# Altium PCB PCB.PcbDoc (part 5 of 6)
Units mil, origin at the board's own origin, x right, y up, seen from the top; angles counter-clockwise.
Board outline 7100 x 7000 mil, 4 copper layers (Top Layer, GND, VCC, Bottom Layer), stack 61.2 mil thick; 759 components, 507 nets, 2200 pads, 452 vias.
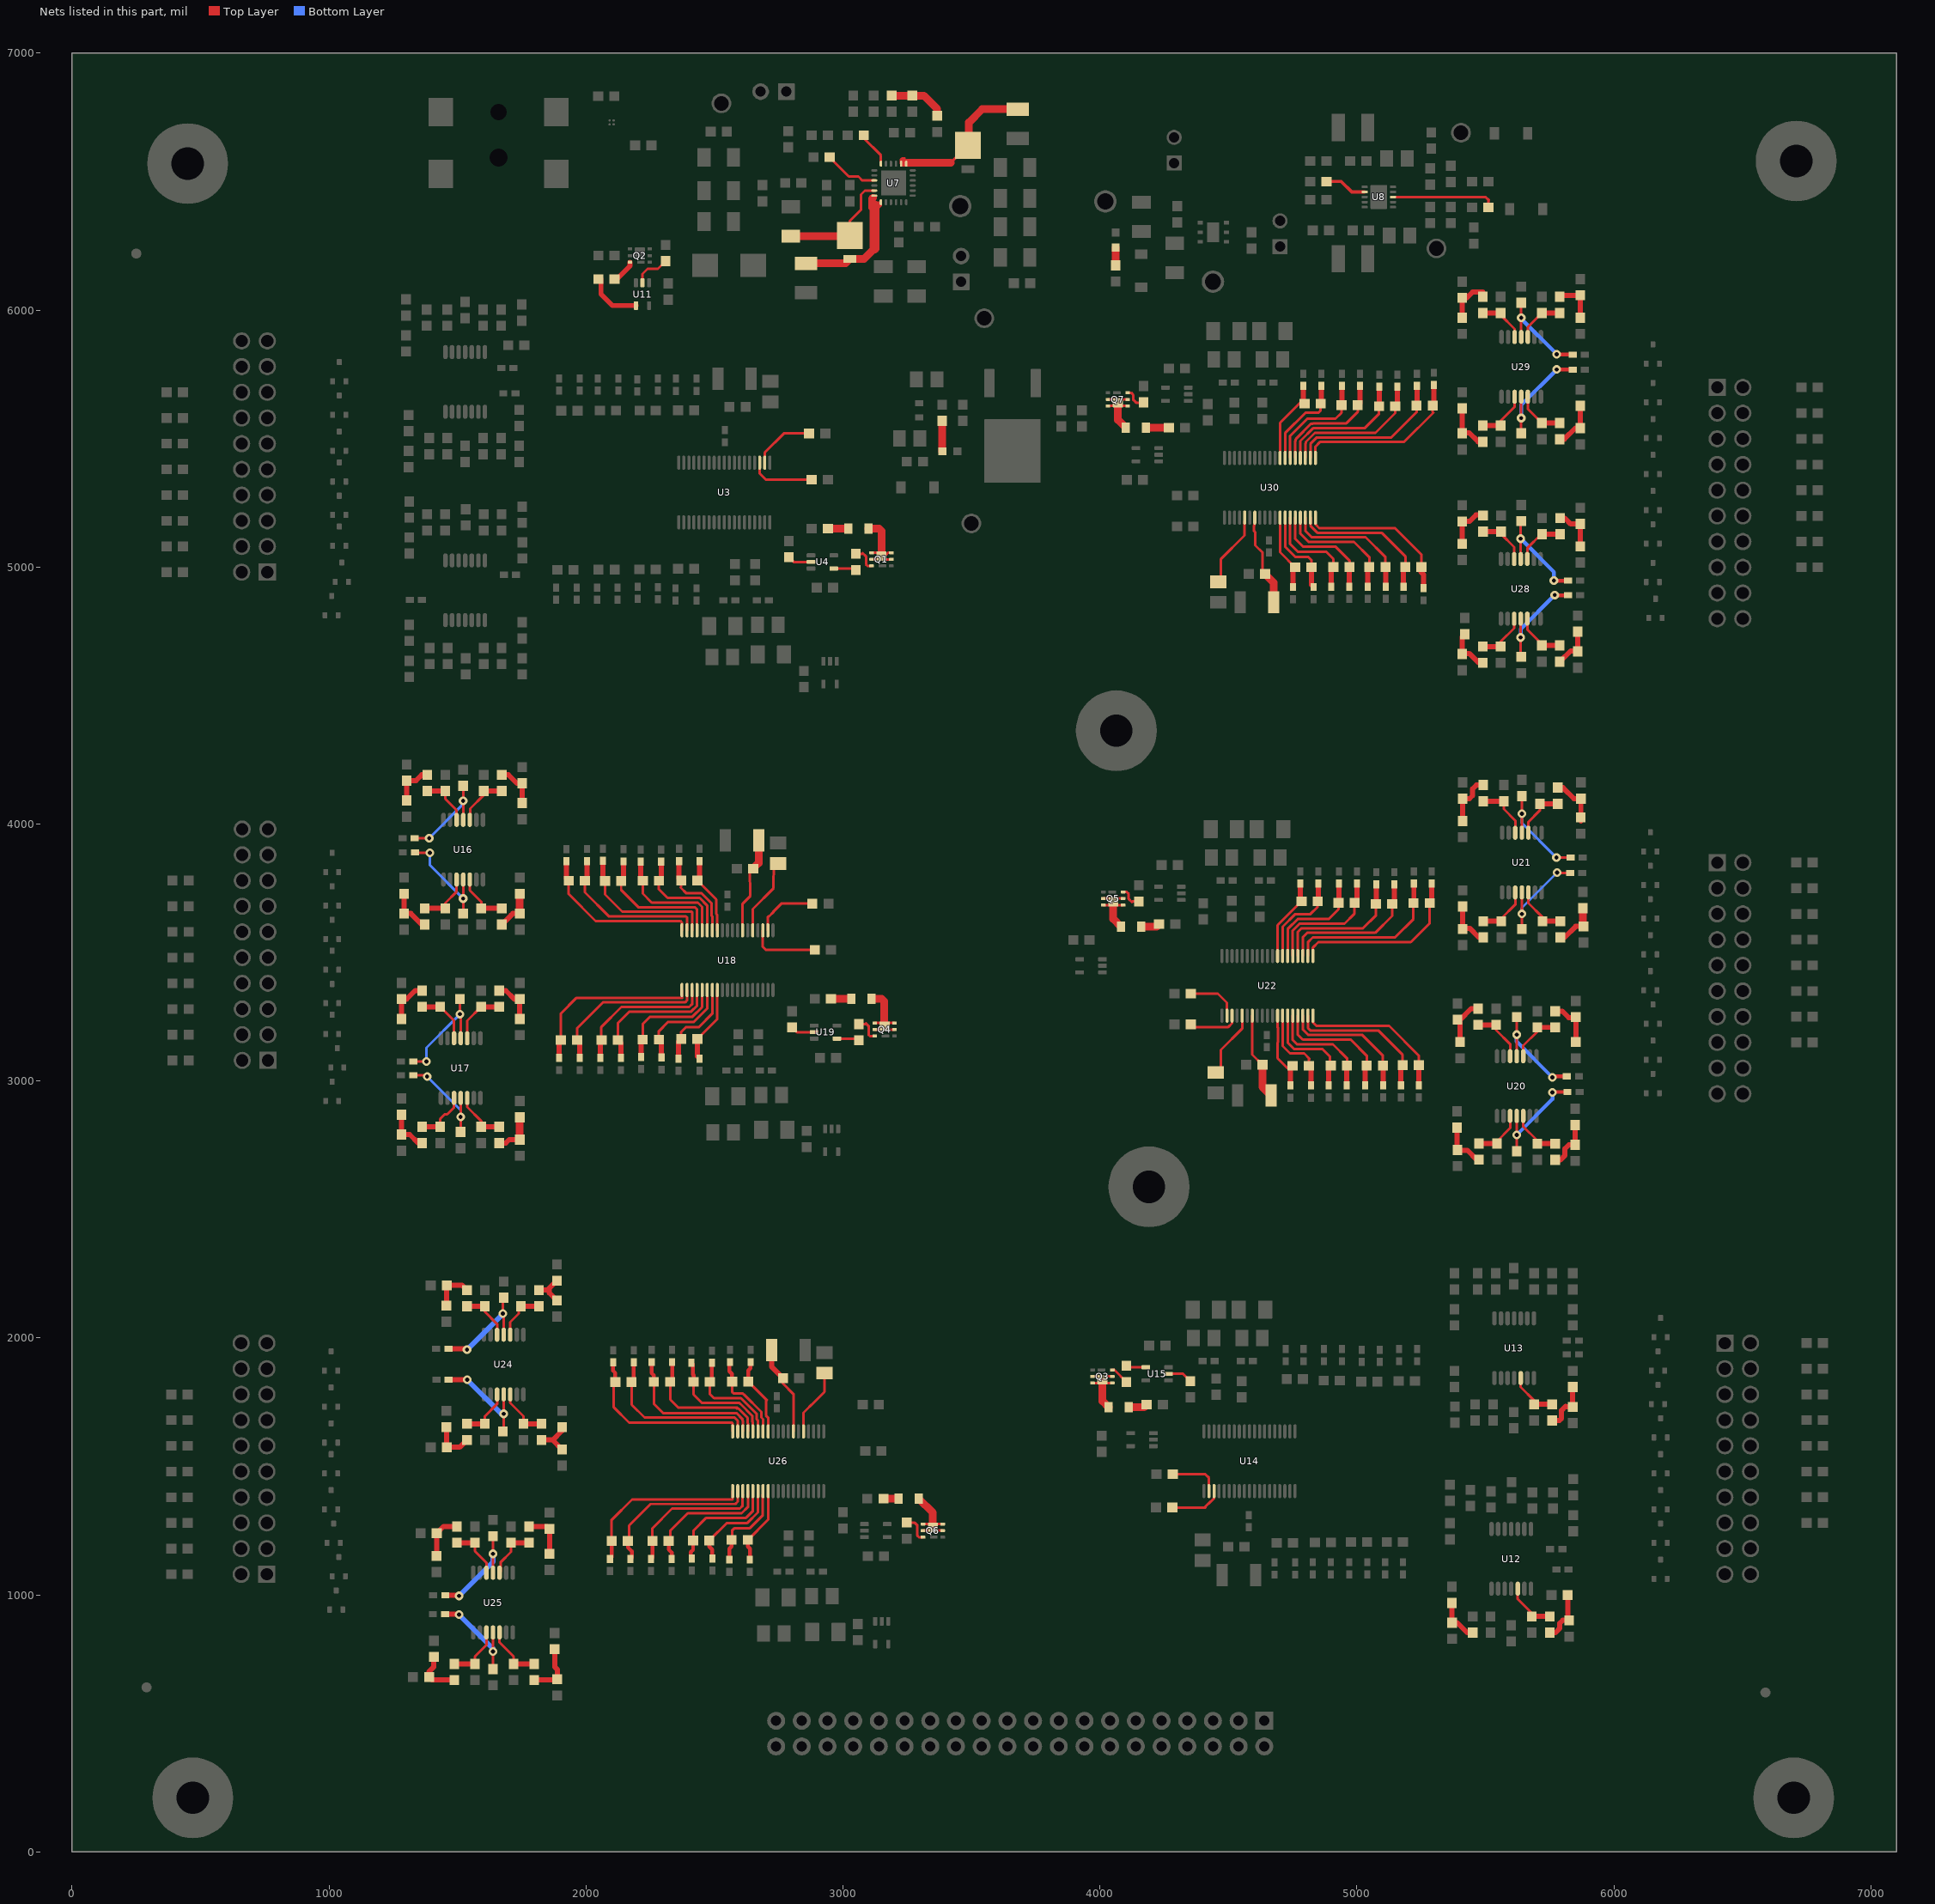
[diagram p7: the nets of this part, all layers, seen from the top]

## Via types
v1: diameter 34, hole 16, Top Layer to Bottom Layer, 440 vias
v2: diameter 19.68, hole 7.87, Top Layer to Bottom Layer, 11 vias
v3: diameter 30, hole 14, Top Layer to Bottom Layer, 1 vias

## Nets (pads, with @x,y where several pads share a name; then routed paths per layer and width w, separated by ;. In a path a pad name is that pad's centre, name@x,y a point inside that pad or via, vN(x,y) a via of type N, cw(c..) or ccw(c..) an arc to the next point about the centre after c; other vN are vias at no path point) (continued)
NetC108_2: C108.2 R109.2 R110.1 | length 173.3
  Top Layer w20: C108.2@5370,968.5 5370,892.22 R109.2@5370.73,891.5 5390.69,891.5 5429.23,852.95 R110.1@5450.73,852.95
NetC110_2: C110.2 R113.2 U12.5 | length 200.5
  Top Layer w10: U12.5@5626.32,1023.86 5626.32,983.68 5680.73,929.27 C110.2@5680.73,915.94
  Top Layer w20: C110.2@5680.73,915.94 R113.2@5750.73,915.94
NetC111_2: C111.2 R117.2 U13.5 | length 194.1
  Top Layer w10: U13.5@5637.64,1843.86 5637.64,1808.82 5690,1756.46 C111.2@5690,1741.5
  Top Layer w20: C111.2@5690,1741.5 R117.2@5760,1741.5
NetC112_2: C112.2 R112.2 R113.1 | length 203
  Top Layer w20: R113.1@5750.73,852.95 5772.95,852.95 5790,870 5790,890 5801.5,901.5 5830.73,901.5 5820.73,911.5 C112.2@5820.73,988.5
NetC113_2: C113.2 R116.2 R117.1 | length 199.3
  Top Layer w20: R117.1@5760,1678.5 5788.5,1678.5 5796.57,1686.57 5796.57,1717.84 5812.73,1734 5815.24,1731.5 R116.2@5840,1731.5 C113.2@5840,1808.5
NetC114_2: C114.2 R319.2 U16.4 | length 388.6
  Top Layer w10: R319.2@1333.62,3945 v1(1390,3945) ; U16.4@1522.36,4016.14 v1(1522.36,4090) C114.2@1522.36,4148.5
  Bottom Layer w10: v1(1390,3945) 1522.36,4077.36 v1(1522.36,4090)
NetC115_2: C115.2 R320.2 U17.4 | length 443.4
  Top Layer w10: R320.2@1327.62,3075 1378,3075 v1(1379,3076) ; C115.2@1510,3318.5 v1(1510,3260) 1512.36,3257.64 U17.4@1512.36,3166.14
  Bottom Layer w10: v1(1379,3076) 1379,3129 v1(1510,3260)
NetC116_2: C116.2 R119.2 U16.10 | length 210.8
  Top Layer w10: C116.2@1452.36,3671.5 1452.36,3692.36 1496.77,3736.77 U16.10@1496.77,3783.86
  Top Layer w20: R119.2@1372.36,3671.5 C116.2@1452.36,3671.5
NetC117_2: C117.2 R121.2 U17.10 | length 210.8
  Top Layer w10: C117.2@1432.36,2821.5 1432.36,2852.36 1450,2870 1460,2870 1486.77,2896.77 U17.10@1486.77,2933.86
  Top Layer w20: R121.2@1362.36,2821.5 C117.2@1432.36,2821.5
NetC124_2: C124.2 R321.2 U16.11 | length 422.7
  Top Layer w10: R321.2@1334.62,3889 1335.62,3888 v1(1393,3888) ; C124.2@1522.36,3651.5 v1(1522.36,3710) U16.11@1522.36,3783.86
  Bottom Layer w10: v1(1393,3888) 1393,3839.36 v1(1522.36,3710)
NetC125_2: C125.2 R322.2 U17.11 | length 399.8
  Top Layer w10: R322.2@1327.62,3022 1377,3022 v1(1382,3017) ; C125.2@1512.36,2801.5 v1(1512.36,2860) U17.11@1512.36,2933.86
  Bottom Layer w10: v1(1382,3017) 1512.36,2886.64 v1(1512.36,2860)
NetC126_2: C126.2 R118.2 R119.1 | length 174.8
  Top Layer w20: C126.2@1292.36,3728.5 R118.2@1292.36,3651.5 1318.5,3651.5 1361.5,3608.5 R119.1@1372.36,3608.5
NetC127_2: C127.2 R120.2 R121.1 | length 170.7
  Top Layer w20: C127.2@1282.36,2868.5 R120.2@1282.36,2791.5 1314.13,2791.5 1347.13,2758.5 R121.1@1362.36,2758.5
NetC128_1: C128.1 R130.2 U18.16 | length 523.2
  Top Layer w10: C128.1@2137.05,3778.12 2137.05,3742.95 2203.62,3676.38 2423.62,3676.38 2432.51,3667.49 U18.16@2432.51,3586.09
  Top Layer w20: C128.1@2137.05,3778.12 2145.55,3786.62 R130.2@2145.55,3854.5
NetC128_2: C128.2 R131.2 U18.17 | length 572.3
  Top Layer w10: C128.2@2074.06,3778.12 2074.06,3725.94 2141.5,3658.5 2411.5,3658.5 2412.82,3657.18 U18.17@2412.82,3586.09
  Top Layer w20: R131.2@2065.55,3856.38 2065.55,3786.62 C128.2@2074.06,3778.12
NetC129_1: C129.1 R132.2 U18.18 | length 613.9
  Top Layer w10: C129.1@1995.94,3778.7 1995.94,3734.06 2090,3640 2090.63,3640.63 2389.37,3640.63 2393.14,3636.86 U18.18@2393.14,3586.09
  Top Layer w20: C129.1@1995.94,3778.7 2004.45,3787.2 R132.2@2004.45,3855.64
NetC129_2: C129.2 R134.2 U18.19 | length 648.8
  Top Layer w10: C129.2@1932.95,3778.7 1932.95,3727.05 2037.64,3622.36 2082.36,3622.36 2082.6,3622.13 2097.4,3622.13 2098.03,3622.76 2367.24,3622.76 2373.45,3616.55 U18.19@2373.45,3586.09
  Top Layer w20: R134.2@1924.45,3855.08 1924.45,3787.2 C129.2@1932.95,3778.7
NetC130_2: C130.2 R136.2 U16.12 | length 210.8
  Top Layer w10: U16.12@1547.95,3783.86 1547.95,3742.05 1592.36,3697.64 C130.2@1592.36,3671.5
  Top Layer w20: C130.2@1592.36,3671.5 R136.2@1672.36,3671.5
NetC131_2: C131.2 R138.2 U17.12 | length 204.9
  Top Layer w10: U17.12@1537.95,2933.86 1537.95,2898.5 1592.36,2844.09 C131.2@1592.36,2821.5
  Top Layer w20: C131.2@1592.36,2821.5 R138.2@1662.36,2821.5
NetC132_1: C132.1 R139.2 U18.21 | length 633.2
  Top Layer w10: C132.1@1965.41,3159.59 1965.41,3205.41 2065.75,3305.75 2385.75,3305.75 2393.14,3313.14 U18.21@2393.14,3353.8
  Top Layer w20: C132.1@1965.41,3159.59 1975.86,3149.13 R139.2@1975.86,3089.59
NetC132_2: C132.2 R141.2 U18.20 | length 704.5
  Top Layer w10: C132.2@1902.42,3159.59 1902.42,3262.42 1963.62,3323.62 2375.11,3323.62 2373.45,3325.28 U18.20@2373.45,3353.8
  Top Layer w20: R141.2@1895.86,3089.59 1895.86,3153.03 C132.2@1902.42,3159.59
NetC133_1: C133.1 R142.2 U18.23 | length 537.1
  Top Layer w10: C133.1@2124.11,3159.59 2124.11,3224.11 2170,3270 2409.44,3270 2432.51,3293.06 U18.23@2432.51,3353.8
  Top Layer w20: C133.1@2124.11,3159.59 2135.88,3147.81 R142.2@2135.88,3089.59
NetC133_2: C133.2 R143.2 U18.22 | length 567.7
  Top Layer w10: C133.2@2061.12,3159.59 2060,3160.71 2060,3210 2137.87,3287.87 2402.04,3287.87 2412.82,3298.66 U18.22@2412.82,3353.8
  Top Layer w20: R143.2@2055.88,3089.59 2055.88,3154.35 C133.2@2061.12,3159.59
NetC134_1: C134.1 R144.2 U18.25 | length 403.3
  Top Layer w10: C134.1@2283.86,3161.22 2283.86,3193.86 2320,3230 2420,3230 2471.88,3281.88 U18.25@2471.88,3353.8
  Top Layer w20: C134.1@2283.86,3161.22 2294.09,3150.99 R144.2@2294.09,3091.22
NetC134_2: C134.2 R145.2 U18.24 | length 455.3
  Top Layer w10: C134.2@2220.87,3161.22 2220.87,3220.87 2250,3250 2414.72,3250 2452.19,3287.47 U18.24@2452.19,3353.8
  Top Layer w20: R145.2@2214.09,3093.62 2214.09,3154.45 C134.2@2220.87,3161.22
NetC135_2: C135.2 R135.2 R136.1 | length 165.2
  Top Layer w20: R136.1@1672.36,3608.5 1673.03,3608.5 1708.94,3644.41 1708.94,3645.08 1715.35,3651.5 R135.2@1742.36,3651.5
  Top Layer w30: R135.2@1742.36,3651.5 C135.2@1742.36,3728.5
NetC136_2: C136.2 R137.2 R138.1 | length 172.4
  Top Layer w20: R138.1@1662.36,2758.5 1688.5,2758.5 1701.5,2771.5 R137.2@1742.36,2771.5
  Top Layer w30: R137.2@1742.36,2771.5 C136.2@1742.36,2858.5
NetC137_1: C137.1 U18.5 | length 322.4
  Top Layer w10: U18.5@2649.04,3586.09 2649.04,3669.04 2730,3750 C137.1@2731,3850 ; C137.1@2730,3828.64 C137.1@2747.62,3846.26
NetC138_1: C138.1 C139.1 U18.7 | length 387.1
  Top Layer w10: U18.7@2609.67,3586.09 2609.67,3689.67 2640,3720 C139.1@2638.06,3826.26 ; C139.1@2640,3815.4 C139.1@2650.86,3826.26
  Top Layer w30: C139.1@2650.86,3826.26 2672.58,3847.98 C138.1@2672.58,3936.26
NetC140_1: C140.1 R146.2 U18.27 | length 302.2
  Top Layer w10: C140.1@2433.86,3163.57 2511.25,3240.96 U18.27@2511.25,3353.8
  Top Layer w20: C140.1@2433.86,3163.57 2433.86,3095.7 R146.2@2442.36,3087.19
NetC140_2: C140.2 R147.2 U18.26 | length 350.1
  Top Layer w10: C140.2@2370.87,3163.57 2370.87,3190.87 2390,3210 2440,3210 2491.56,3261.56 U18.26@2491.56,3353.8
  Top Layer w20: R147.2@2360.62,3087.19 2360.62,3153.32 C140.2@2370.87,3163.57
NetC141_1: C141.1 R148.2 U18.12 | length 305.3
  Top Layer w10: C141.1@2433.86,3779.95 2507.44,3706.37 2507.44,3649.89 2511.25,3646.09 U18.12@2511.25,3586.09
  Top Layer w20: C141.1@2433.86,3779.95 2442.36,3788.45 R148.2@2442.36,3855.82
NetC141_2: C141.2 R149.2 U18.13 | length 359.8
  Top Layer w10: C141.2@2370.87,3779.95 2370.87,3755.19 2368.36,3752.68 2391.05,3730 2450,3730 2489.57,3690.43 2489.57,3642.49 2491.56,3640.49 U18.13@2491.56,3586.09
  Top Layer w20: R149.2@2362.57,3855.82 2362.57,3788.25 C141.2@2370.87,3779.95
NetC142_1: C142.1 R150.2 U18.14 | length 421.8
  Top Layer w10: C142.1@2284.06,3779.44 2284.06,3745.94 2317.87,3712.13 2442.6,3712.13 2471.69,3683.03 2471.69,3635.09 2471.88,3634.9 U18.14@2471.88,3586.09
  Top Layer w20: C142.1@2284.06,3779.44 2292.57,3787.94 R150.2@2292.57,3853.53
NetC142_2: C142.2 R151.2 U18.15 | length 471.8
  Top Layer w10: C142.2@2221.07,3779.44 2221.07,3728.93 2255.75,3694.25 2435.19,3694.25 2452.19,3677.25 U18.15@2452.19,3586.09
  Top Layer w20: R151.2@2212.57,3853.53 2212.57,3787.94 C142.2@2221.07,3779.44
NetC143_2: C143.2 R153.2 U17.3 | length 214.9
  Top Layer w10: U17.3@1537.95,3166.14 1537.95,3234.09 C143.2@1592.36,3288.5
  Top Layer w20: C143.2@1592.36,3288.5 R153.2@1662.36,3288.5
NetC144_2: C144.2 R155.2 U16.3 | length 204.9
  Top Layer w10: U16.3@1547.95,4016.14 1550,4018.19 1550,4060 1602.36,4112.36 C144.2@1602.36,4128.5
  Top Layer w20: C144.2@1602.36,4128.5 R155.2@1672.36,4128.5
NetC145_2: C145.2 R152.2 R153.1 | length 170.7
  Top Layer w20: R153.1@1662.36,3351.5 1688.5,3351.5 1721.5,3318.5 R152.2@1742.36,3318.5 C145.2@1742.36,3241.5
NetC146_2: C146.2 R154.2 R155.1 | length 170.7
  Top Layer w20: R155.1@1672.36,4191.5 1698.5,4191.5 1731.5,4158.5 R154.2@1752.36,4158.5 C146.2@1752.36,4081.5
NetC148_2: C148.2 R158.2 U16.5 | length 200.8
  Top Layer w10: C148.2@1452.36,4128.5 1452.36,4097.64 1496.77,4053.23 U16.5@1496.77,4016.14
  Top Layer w20: R158.2@1382.36,4128.5 C148.2@1452.36,4128.5
NetC149_2: C149.2 R162.2 U17.5 | length 214.9
  Top Layer w10: C149.2@1432.36,3288.5 1486.77,3234.09 U17.5@1486.77,3166.14
  Top Layer w20: R162.2@1362.36,3288.5 C149.2@1432.36,3288.5
NetC150_2: C150.2 R157.2 R158.1 | length 166.5
  Top Layer w20: C150.2@1302.36,4091.5 R157.2@1302.36,4168.5 1338.5,4168.5 1361.5,4191.5 R158.1@1382.36,4191.5
NetC151_2: C151.2 R161.2 R162.1 | length 170.7
  Top Layer w20: C151.2@1282.36,3241.5 R161.2@1282.36,3318.5 1302.32,3318.5 1335.31,3351.5 R162.1@1362.36,3351.5
NetC152_2: C152.2 R324.2 U20.4 | length 419.7
  Top Layer w10: C152.2@5622.05,2725.94 v1(5622.05,2790) U20.4@5622.05,2863.86
  Top Layer w15: v1(5761,2955) 5763,2957 R324.2@5819.38,2957
  Bottom Layer w15: v1(5622.05,2790) 5761,2928.95 v1(5761,2955)
NetC153_2: C153.2 R325.2 U21.4 | length 411.9
  Top Layer w10: C153.2@5642.05,3591.5 v1(5642.05,3650) U21.4@5642.05,3733.86 ; v1(5779,3811) 5780,3810 R325.2@5830.38,3810
  Bottom Layer w10: v1(5642.05,3650) 5642.05,3674.05 v1(5779,3811)
NetC154_2: C154.2 R164.2 U20.10 | length 204.9
  Top Layer w10: U20.10@5647.64,3096.14 5647.64,3137.64 5702.05,3192.05 C154.2@5702.05,3208.5
  Top Layer w20: C154.2@5702.05,3208.5 R164.2@5772.05,3208.5
NetC155_2: C155.2 R166.2 U21.10 | length 200.8
  Top Layer w10: U21.10@5667.64,3966.14 5667.64,4007.64 5712.05,4052.05 C155.2@5712.05,4078.5
  Top Layer w20: C155.2@5712.05,4078.5 R166.2@5782.05,4078.5
NetC162_2: C162.2 R326.2 U20.11 | length 434
  Top Layer w10: U20.11@5622.05,3096.14 v1(5622.05,3180) C162.2@5622.05,3248.5
  Top Layer w15: v1(5761,3014) 5765,3018 R326.2@5817.38,3018
  Bottom Layer w15: v1(5622.05,3180) 5622.05,3152.95 v1(5761,3014)
NetC163_2: C163.2 R327.2 U21.11 | length 424.1
  Top Layer w10: U21.11@5642.05,3966.14 v1(5642.05,4040) C163.2@5642.05,4108.5 ; v1(5777,3869) 5778,3870 R327.2@5831.38,3870
  Bottom Layer w10: v1(5642.05,4040) 5642.05,4003.95 v1(5777,3869)
NetC164_2: C164.2 R163.2 R164.1 | length 188.6
  Top Layer w20: R164.1@5772.05,3271.5 5799.35,3271.5 5824.85,3246 5849.54,3246 R163.2@5852.05,3248.5 C164.2@5852.05,3151.5
NetC165_2: C165.2 R165.2 R166.1 | length 194.8
  Top Layer w20: R166.1@5782.05,4141.5 5802.01,4141.5 5845,4098.5 R165.2@5872.05,4098.5 C165.2@5872.05,4011.5
NetC166_1: C166.1 R175.2 U22.16 | length 494
  Top Layer w10: U22.16@4770.16,3254.17 4770.16,3179.84 4789.33,3160.67 4976.34,3160.67 5038.5,3098.5 C166.1@5038.5,3060
  Top Layer w20: R175.2@5031.81,2983.62 5031.81,3053.31 C166.1@5038.5,3060
NetC166_2: C166.2 R176.2 U22.17 | length 522.8
  Top Layer w10: U22.17@4789.84,3254.17 4789.84,3200.16 4811.46,3178.54 5021.46,3178.54 5101.5,3098.5 C166.2@5101.5,3060
  Top Layer w20: C166.2@5101.5,3060 5101.81,3059.69 R176.2@5101.81,2983.62
NetC167_1: C167.1 R177.2 U22.18 | length 581.2
  Top Layer w10: U22.18@4809.53,3254.17 4809.53,3220.47 4810,3220 4810,3205.28 4818.86,3196.42 5083.58,3196.42 5178.5,3101.5 C167.1@5178.5,3061.65
  Top Layer w20: R177.2@5171.81,2983.62 5171.81,3054.96 C167.1@5178.5,3061.65
NetC167_2: C167.2 R179.2 U22.19 | length 607.4
  Top Layer w10: U22.19@4829.21,3254.17 4829.21,3227.56 4842.48,3214.29 5125.71,3214.29 5241.5,3098.5 C167.2@5241.5,3061.65
  Top Layer w20: C167.2@5241.5,3061.65 5241.81,3061.34 R179.2@5241.81,2983.62
NetC168_2: C168.2 R181.2 U20.12 | length 214.9
  Top Layer w10: C168.2@5542.05,3218.5 5542.05,3197.95 5596.46,3143.54 U20.12@5596.46,3096.14
  Top Layer w20: R181.2@5472.05,3218.5 C168.2@5542.05,3218.5
NetC169_2: C169.2 R183.2 U21.12 | length 220.8
  Top Layer w10: C169.2@5572.05,4088.5 5572.05,4057.95 5616.46,4013.54 U21.12@5616.46,3966.14
  Top Layer w20: R183.2@5492.05,4088.5 C169.2@5572.05,4088.5
NetC170_1: C170.1 R184.2 U22.21 | length 640
  Top Layer w10: U22.21@4809.53,3486.46 4809.53,3539.53 4828.5,3558.5 5148.5,3558.5 5220,3630 5220,3691.36 C170.1@5220.45,3691.81
  Top Layer w20: C170.1@5220.45,3691.81 5221.95,3693.31 R184.2@5221.95,3768.19
NetC170_2: C170.2 R186.2 U22.20 | length 684.3
  Top Layer w10: U22.20@4829.21,3486.46 4829.21,3519.21 4850,3540 5210,3540 5283.45,3613.45 C170.2@5283.45,3691.81
  Top Layer w20: C170.2@5283.45,3691.81 5291.95,3700.32 R186.2@5291.95,3768.19
NetC171_1: C171.1 R187.2 U22.23 | length 545.9
  Top Layer w10: U22.23@4770.16,3486.46 4770.16,3579.6 4784.81,3594.25 5024.25,3594.25 5074.5,3644.5 C171.1@5074.5,3689.01
  Top Layer w20: C171.1@5074.5,3689.01 5076,3690.51 R187.2@5076,3765.39
NetC171_2: C171.2 R188.2 U22.22 | length 581.7
  Top Layer w10: U22.22@4789.84,3486.46 4789.84,3559.84 4806.38,3576.38 5071.37,3576.38 5137.5,3642.5 C171.2@5137.5,3689.01
  Top Layer w20: C171.2@5137.5,3689.01 5146,3697.52 R188.2@5146,3765.39
NetC172_1: C172.1 R189.2 U22.25 | length 434.5
  Top Layer w10: U22.25@4730.79,3486.46 4730.79,3590.79 4770,3630 4890,3630 4928.5,3668.5 C172.1@4928.5,3693.31
  Top Layer w20: C172.1@4928.5,3693.31 4930,3694.8 R189.2@4930,3768.19
NetC172_2: C172.2 R190.2 U22.24 | length 487.4
  Top Layer w10: U22.24@4750.47,3486.46 4750.47,3585.19 4777.4,3612.13 4952.13,3612.13 4990,3650 4990,3691.81 C172.2@4991.5,3693.31
  Top Layer w20: C172.2@4991.5,3693.31 5000,3701.81 R190.2@5000,3768.19
NetC173_2: C173.2 R180.2 R181.1 | length 189
  Top Layer w20: C173.2@5402.05,3151.5 5402.05,3228.5 R180.2@5392.05,3238.5 5402.01,3238.5 5445,3281.5 R181.1@5472.05,3281.5
NetC174_2: C174.2 R182.2 R183.1 | length 204.5
  Top Layer w20: C174.2@5412.05,4011.5 R182.2@5412.05,4098.5 5438.5,4098.5 5450,4110 5450,4136.5 5465,4151.5 R183.1@5492.05,4151.5
NetC175_1: C175.1 U22.5 | length 263.7
  Top Layer w10: C175.1@4451,3033 4471,3053 4471,3121 4553.62,3203.62 U22.5@4553.62,3254.17
NetC176_1: C176.1 C177.1 U22.7 | length 341.4
  Top Layer w10: U22.7@4592.99,3254.17 4592.99,3102.5 C177.1@4632.5,3063
  Top Layer w30: C177.1@4632.5,3063 4632.5,2976.46 C176.1@4665.96,2943
NetC178_1: C178.1 R191.2 U22.27 | length 322.2
  Top Layer w10: U22.27@4691.42,3486.46 4691.42,3605.92 C178.1@4784.5,3699.01
  Top Layer w20: R191.2@4780,3768.19 4780,3703.52 C178.1@4784.5,3699.01
NetC178_2: C178.2 R192.2 U22.26 | length 374
  Top Layer w10: U22.26@4711.1,3486.46 4711.1,3600.33 4760.39,3649.61 4819.61,3649.61 4847.5,3677.5 C178.2@4847.5,3699.01
  Top Layer w20: C178.2@4847.5,3699.01 4850,3701.52 R192.2@4850,3768.19
NetC179_1: C179.1 R193.2 U22.12 | length 324.9
  Top Layer w10: U22.12@4691.42,3254.17 4691.42,3208.25 4692.56,3207.11 4692.56,3150.14 4691.42,3149 4691.42,3147.19 4691.42,3088.58 4730,3050 4738.7,3058.7 C179.1@4750.31,3058.7
  Top Layer w20: R193.2@4741.81,2982.32 4741.81,3050.2 C179.1@4750.31,3058.7
NetC179_2: C179.2 R194.2 U22.13 | length 351.7
  Top Layer w10: U22.13@4711.1,3254.17 4711.1,3136.1 4740.16,3107.05 4794.73,3107.05 4815.81,3085.97 4813.31,3083.46 C179.2@4813.31,3058.7
  Top Layer w20: C179.2@4813.31,3058.7 4821.81,3050.2 R194.2@4821.81,2982.32
NetC180_1: C180.1 R195.2 U22.14 | length 408
  Top Layer w10: U22.14@4730.79,3254.17 4730.79,3149.21 4755.08,3124.92 4865.08,3124.92 4894.47,3095.53 4894.47,3064.05 C180.1@4898.52,3060
  Top Layer w20: R195.2@4890.02,2983.62 4890.02,3051.5 C180.1@4898.52,3060
NetC180_2: C180.2 R196.2 U22.15 | length 440.6
  Top Layer w10: U22.15@4750.47,3254.17 4750.47,3159.53 4767.2,3142.8 4907.2,3142.8 4961.52,3088.48 C180.2@4961.52,3060
  Top Layer w20: R196.2@4960.02,2983.62 4960.02,3058.5 C180.2@4961.52,3060
NetC181_2: C181.2 R198.2 U21.3 | length 201.8
  Top Layer w10: C181.2@5562.05,3626.77 5562.05,3632.05 5616.46,3686.46 U21.3@5616.46,3733.86
  Top Layer w20: R198.2@5492.05,3621.5 5556.77,3621.5 C181.2@5562.05,3626.77
NetC182_2: C182.2 R200.2 U20.3 | length 198.7
  Top Layer w10: C182.2@5545,2756.48 5545,2765 5596.46,2816.46 U20.3@5596.46,2863.86
  Top Layer w20: R200.2@5475,2756.48 C182.2@5545,2756.48
NetC183_2: C183.2 R197.2 R198.1 | length 182.7
  Top Layer w20: C183.2@5412.05,3678.5 R197.2@5412.05,3591.5 5414.55,3594 5439.25,3594 5474.74,3558.5 R198.1@5492.05,3558.5
NetC184_2: C184.2 R199.2 R200.1 | length 186.6
  Top Layer w20: C184.2@5390,2818.5 5390,2733.54 R199.2@5392.05,2731.5 5393.54,2730 5430,2730 5466.51,2693.49 R200.1@5475,2693.49
NetC186_2: C186.2 R203.2 U20.5 | length 200.5
  Top Layer w10: U20.5@5647.64,2863.86 5647.64,2822.36 5702.05,2767.95 C186.2@5702.05,2755.94
  Top Layer w20: C186.2@5702.05,2755.94 R203.2@5772.05,2755.94
NetC187_2: C187.2 R207.2 U21.5 | length 204.9
  Top Layer w10: U21.5@5667.64,3733.86 5667.64,3692.36 5722.05,3637.95 C187.2@5722.05,3621.5
  Top Layer w20: C187.2@5722.05,3621.5 R207.2@5792.05,3621.5
NetC188_2: C188.2 R202.2 R203.1 | length 194.6
  Top Layer w20: R203.1@5772.05,2692.95 5792.95,2692.95 5810,2710 5810,2736.26 5825.24,2751.5 R202.2@5850,2751.5 C188.2@5850,2828.5
NetC189_2: C189.2 R206.2 R207.1 | length 179.7
  Top Layer w20: R207.1@5792.05,3558.5 5808.5,3558.5 5851.5,3601.5 R206.2@5882.05,3601.5
  Top Layer w30: C189.2@5880,3672.5 5880,3603.54 R206.2@5882.05,3601.5
NetC190_2: C190.2 R329.2 U24.4 | length 418.2
  Top Layer w10: U24.4@1679.76,2012.57 1679.76,2091.6 v1(1676.96,2094.4) 1676.96,2153.63 C190.2@1679.76,2156.43
  Top Layer w20: R329.2@1464.62,1957 1534,1957 v1(1537,1954)
  Bottom Layer w20: v1(1537,1954) 1676.96,2093.96 v1(1676.96,2094.4)
NetC191_2: C191.2 R330.2 U25.4 | length 415.3
  Top Layer w10: U25.4@1638.26,1086.09 v1(1638.26,1159.95) C191.2@1638.26,1228.45
  Top Layer w20: R330.2@1452.62,998 1503,998 1505,996 v1(1506,996)
  Bottom Layer w20: v1(1506,996) 1638.26,1128.26 v1(1638.26,1159.95)
NetC192_2: C192.2 R209.2 U24.10 | length 203.9
  Top Layer w10: C192.2@1606.96,1665.9 1606.96,1695.42 1654.17,1742.63 U24.10@1654.17,1780.29
  Top Layer w20: R209.2@1536.96,1665.9 C192.2@1606.96,1665.9
NetC193_2: C193.2 R211.2 U25.10 | length 220.8
  Top Layer w10: C193.2@1568.26,731.45 1568.26,759.95 1612.67,804.36 U25.10@1612.67,853.81
  Top Layer w20: R211.2@1488.26,731.45 C193.2@1568.26,731.45
NetC200_2: C200.2 R331.2 U24.11 | length 414.6
  Top Layer w10: C200.2@1676.96,1635.9 1679.76,1638.7 v1(1679.76,1704.4) U24.11@1679.76,1780.29
  Top Layer w20: R331.2@1465.62,1837 v1(1538,1837)
  Bottom Layer w20: v1(1538,1837) 1670.6,1704.4 v1(1679.76,1704.4)
NetC201_2: C201.2 R332.2 U25.11 | length 395.4
  Top Layer w10: C201.2@1638.26,711.45 v1(1638.26,779.95) U25.11@1638.26,853.81
  Top Layer w20: R332.2@1451.62,925 1504,925 v1(1506,923)
  Bottom Layer w20: v1(1506,923) 1638.26,790.74 v1(1638.26,779.95)
NetC202_2: C202.2 R208.2 R209.1 | length 169.4
  Top Layer w20: C202.2@1456.96,1652.9 1458.45,1651.41 R208.2@1458.45,1574.4 1508.45,1574.4 R209.1@1536.96,1602.9
NetC203_2: C203.2 R210.2 R211.1 | length 189.4
  Top Layer w20: C203.2@1408.26,758.45 1408.26,719.95 1389.75,701.45 R210.2@1389.75,679.95 1401.25,668.45 R211.1@1488.26,668.45
NetC204_1: C204.1 R220.2 U26.16 | length 539
  Top Layer w10: C204.1@2327.25,1829.44 2328.26,1828.44 2328.26,1759.95 2359.91,1728.3 2588.26,1728.3 2585.66,1725.7 2593.06,1725.7 2626.52,1692.24 2626.52,1691.68 2628.95,1689.26 2628.95,1668.28 2630.15,1667.08 U26.16@2630.15,1636.09
  Top Layer w15: C204.1@2327.25,1829.44 2335.76,1837.94 R220.2@2335.76,1905.82
NetC204_2: C204.2 R221.2 U26.17 | length 583.8
  Top Layer w10: C204.2@2264.26,1829.44 2264.26,1743.95 2300.38,1707.82 2585.66,1707.82 2608.65,1684.83 2608.65,1679.56 2610.46,1677.75 U26.17@2610.46,1636.09
  Top Layer w15: R221.2@2255.76,1905.82 2255.76,1862.64 2264.26,1854.14 C204.2@2264.26,1829.44
NetC205_1: C205.1 R222.2 U26.18 | length 648.2
  Top Layer w10: C205.1@2177.27,1828.12 2178.26,1827.14 2178.26,1739.95 2228.26,1689.95 2578.26,1689.95 2590.78,1677.43 U26.18@2590.78,1636.09
  Top Layer w15: C205.1@2177.27,1828.12 2185.78,1836.62 R222.2@2185.78,1904.5
NetC205_2: C205.2 R224.2 U26.19 | length 700.5
  Top Layer w10: C205.2@2114.28,1828.12 2108.26,1822.1 2108.26,1729.95 2168.26,1669.95 2568.26,1669.95 2571.09,1667.12 U26.19@2571.09,1636.09
  Top Layer w15: R224.2@2105.78,1904.5 2105.78,1872.43 2114.28,1863.93 C205.2@2114.28,1828.12
NetC206_2: C206.2 R226.2 U24.12 | length 205.8
  Top Layer w10: U24.12@1705.35,1780.29 1705.35,1747.03 1756.96,1695.42 C206.2@1756.96,1665.9
  Top Layer w20: C206.2@1756.96,1665.9 R226.2@1826.96,1665.9
NetC207_2: C207.2 R228.2 U25.12 | length 224.9
  Top Layer w10: U25.12@1663.85,853.81 1663.85,814.36 1718.26,759.95 C207.2@1718.26,731.45
  Top Layer w20: C207.2@1718.26,731.45 R228.2@1798.26,731.45
NetC208_1: C208.1 R229.2 U26.21 | length 643
  Top Layer w10: C208.1@2163.05,1209.59 2168.26,1214.8 2168.26,1269.95 2251.88,1353.57 2581.88,1353.57 2590.78,1362.47 U26.21@2590.78,1403.81
  Top Layer w15: C208.1@2163.05,1209.59 2163.05,1185.16 2178.26,1169.95 2178.26,1144.34 R229.2@2173.5,1139.59
NetC208_2: C208.2 R231.2 U26.20 | length 691.3
  Top Layer w10: C208.2@2100.06,1209.59 2100.06,1291.75 2179.75,1371.45 2571.09,1371.45 U26.20@2571.09,1403.81
  Top Layer w15: R231.2@2093.5,1139.59 2100.06,1146.14 C208.2@2100.06,1209.59
NetC209_1: C209.1 R232.2 U26.23 | length 519.9
  Top Layer w10: C209.1@2321.75,1209.59 2328.26,1216.09 2328.26,1249.95 2396.13,1317.82 2606.13,1317.82 2630.15,1341.84 U26.23@2630.15,1403.81
  Top Layer w15: C209.1@2321.75,1209.59 2321.75,1176.95 2333.52,1165.18 R232.2@2333.52,1139.59
NetC209_2: C209.2 R233.2 U26.22 | length 553.1
  Top Layer w10: C209.2@2258.76,1209.59 2258.76,1259.45 2335,1335.7 2598.73,1335.7 2609.56,1346.53 2609.56,1388.14 U26.22@2611.37,1389.95
  Top Layer w15: R233.2@2253.52,1139.59 2258.76,1144.82 C209.2@2258.76,1209.59
NetC210_1: C210.1 R234.2 U26.25 | length 392.6
  Top Layer w10: C210.1@2479.96,1211.22 2548.69,1279.95 2628.26,1279.95 2669.52,1321.21 U26.25@2669.52,1403.81
  Top Layer w15: C210.1@2479.96,1211.22 2479.96,1188.25 2491.73,1176.48 R234.2@2491.73,1141.22
NetC210_2: C210.2 R235.2 U26.24 | length 454.7
  Top Layer w10: C210.2@2416.97,1211.22 2418.26,1212.51 2418.26,1249.95 2468.26,1299.95 2622.98,1299.95 2649.83,1326.8 U26.24@2649.83,1403.81
  Top Layer w15: R235.2@2411.73,1141.22 2408.26,1144.69 2408.26,1166.81 2416.97,1175.52 C210.2@2416.97,1211.22
NetC211_2: C211.2 R225.2 R226.1 | length 160.9
  Top Layer w20: R226.1@1826.96,1602.9 1871.21,1602.9 ; R225.2@1906.96,1565.9 1871.21,1601.64 1871.21,1602.9 ; C211.2@1906.96,1652.9 1906.96,1638.65 1871.21,1602.9
NetC212_2: C212.2 R227.2 R228.1 | length 212.4
  Top Layer w20: R228.1@1798.26,668.45 1885.26,668.45 R227.2@1888.26,671.45 1888.26,709.95 1878.26,719.95 C212.2@1878.26,788.45
NetC213_1: C213.1 U26.5 | length 261.3
  Top Layer w10: U26.5@2846.68,1636.09 2846.68,1708.38 2860.13,1721.82 2860.13,1722.37 2877.63,1739.87 2878.18,1739.87 2928.26,1789.95 C213.1@2928.26,1863.26
NetC214_1: C214.1 C215.1 U26.7 | length 352
  Top Layer w10: C215.1@2766.76,1843.26 2766.76,1822.24 2807.31,1781.69 U26.7@2807.31,1636.09
  Top Layer w20: C214.1@2723.3,1953.26 2723.3,1886.72 C215.1@2766.76,1843.26
NetC216_1: C216.1 R236.2 U26.27 | length 302.9
  Top Layer w10: C216.1@2629.75,1213.57 2708.89,1292.71 U26.27@2708.89,1403.81
  Top Layer w15: C216.1@2629.75,1213.57 2629.75,1188.45 2638.26,1179.95 R236.2@2638.26,1137.19
NetC216_2: C216.2 R237.2 U26.26 | length 341.8
  Top Layer w10: C216.2@2566.76,1213.57 2568.26,1215.07 2568.26,1249.95 2578.26,1259.95 2638.26,1259.95 2688.3,1309.99 U26.26@2688.3,1389.95
  Top Layer w15: R237.2@2558.26,1137.19 2558.26,1179.95 2566.76,1188.45 C216.2@2566.76,1213.57
NetC217_1: C217.1 R238.2 U26.12 | length 307.8
  Top Layer w10: C217.1@2631.7,1829.95 2703.62,1758.04 2700.44,1754.86 2700.44,1697.89 2708.89,1689.45 U26.12@2708.89,1636.09
  Top Layer w15: C217.1@2631.7,1829.95 2631.7,1872.94 2640.21,1881.44 R238.2@2640.21,1905.82
NetC217_2: C217.2 R239.2 U26.13 | length 346.5
  Top Layer w10: C217.2@2568.71,1829.95 2568.26,1829.5 2568.26,1789.95 2574.63,1783.57 2610.47,1783.57 2614.72,1779.32 2615.27,1779.32 2682.57,1712.03 2682.57,1690.49 2689.2,1683.86 U26.13@2689.2,1636.09
  Top Layer w15: R239.2@2560.21,1905.82 2558.26,1903.87 2558.26,1869.95 2568.71,1859.5 C217.2@2568.71,1829.95
NetC218_1: C218.1 R240.2 U26.14 | length 410.5
  Top Layer w10: C218.1@2481.7,1829.44 2481.7,1782.25 2498.26,1765.7 2603.06,1765.7 2607.32,1761.45 2607.87,1761.45 2664.69,1704.62 2664.69,1683.09 2668.61,1679.17 2668.61,1637 U26.14@2669.52,1636.09
  Top Layer w15: C218.1@2481.7,1829.44 2490.21,1837.94 R240.2@2490.21,1903.53
NetC218_2: C218.2 R241.2 U26.15 | length 452.5
  Top Layer w10: C218.2@2418.71,1829.44 2418.26,1828.99 2418.26,1779.95 2450.38,1747.82 2595.66,1747.82 2599.91,1743.57 2600.47,1743.57 2646.82,1697.22 2646.82,1675.68 2649.83,1672.67 U26.15@2649.83,1636.09
  Top Layer w15: R241.2@2410.21,1903.53 2416.21,1897.53 2416.21,1856.64 2418.71,1854.14 C218.2@2418.71,1829.44
NetC219_2: C219.2 R243.2 U25.3 | length 205.2
  Top Layer w10: U25.3@1663.85,1086.09 1667.71,1089.95 1667.71,1126.53 1708.26,1167.08 C219.2@1708.26,1202.9
  Top Layer w20: C219.2@1708.26,1202.9 R243.2@1778.26,1202.9
NetC220_2: C220.2 R245.2 U24.3 | length 197.6
  Top Layer w10: U24.3@1705.35,2012.57 1705.35,2061.51 1738.26,2094.42 1738.26,2114.2 C220.2@1746.96,2122.9
  Top Layer w20: C220.2@1746.96,2122.9 R245.2@1816.96,2122.9
NetC221_2: C221.2 R242.2 R243.1 | length 180.8
  Top Layer w20: R243.1@1778.26,1265.9 1849.16,1265.9 R242.2@1858.26,1256.8 C221.2@1858.26,1159.79
NetC222_2: C222.2 R244.2 R245.1 | length 145.3
  Top Layer w20: R245.1@1816.96,2185.9 1849.95,2185.9 1857.92,2193.87 ; C222.2@1886.96,2145.9 1857.92,2174.93 1857.92,2193.87 ; R244.2@1886.96,2222.9 1857.92,2193.87
NetC224_2: C224.2 R248.2 U24.5 | length 199.9
  Top Layer w10: C224.2@1606.96,2122.9 1606.96,2101.25 1654.17,2054.04 U24.5@1654.17,2012.57
  Top Layer w20: R248.2@1536.96,2122.9 C224.2@1606.96,2122.9
NetC225_2: C225.2 R252.2 U25.5 | length 205.2
  Top Layer w10: C225.2@1568.26,1202.9 1568.26,1169.95 1612.67,1125.54 U25.5@1612.67,1086.09
  Top Layer w20: R252.2@1498.26,1202.9 C225.2@1568.26,1202.9
NetC226_2: C226.2 R247.2 R248.1 | length 165.3
  Top Layer w20: C226.2@1456.96,2125.9 1458.45,2127.39 R247.2@1458.45,2204.4 1518.45,2204.4 R248.1@1536.96,2185.9
NetC227_2: C227.2 R251.2 R252.1 | length 178.4
  Top Layer w20: C227.2@1418.26,1151.45 1419.75,1152.94 R251.2@1419.75,1239.95 1445.7,1265.9 R252.1@1498.26,1265.9
NetC228_2: C228.2 R334.2 U28.4 | length 421.1
  Top Layer w10: U28.4@5637.69,4798.83 v1(5637.69,4725.65) 5637.69,4652.47 C228.2@5639.69,4650.47
  Top Layer w15: v1(5770,4891) 5771,4890 R334.2@5821.38,4890
  Bottom Layer w15: v1(5637.69,4725.65) 5637.69,4758.69 v1(5770,4891)
NetC229_2: C229.2 R335.2 U29.4 | length 451.4
  Top Layer w10: C229.2@5639.69,5520.47 v1(5639.69,5580) U29.4@5639.69,5662.83
  Top Layer w15: v1(5778,5769) 5779,5768 R335.2@5840.38,5768
  Bottom Layer w15: v1(5639.69,5580) 5639.69,5630.69 v1(5778,5769)
NetC230_2: C230.2 R254.2 U28.10 | length 192.3
  Top Layer w10: U28.10@5663.28,5031.12 5663.28,5073.28 C230.2@5717.48,5127.48
  Top Layer w20: C230.2@5717.48,5127.48 C230.2@5720.98,5127.48 R254.2@5790.98,5127.48
NetC231_2: C231.2 R256.2 U29.10 | length 185.9
  Top Layer w10: U29.10@5665.28,5895.12 5665.28,5934.09 C231.2@5719.69,5988.5
  Top Layer w20: C231.2@5719.69,5988.5 R256.2@5789.69,5988.5
NetC238_2: C238.2 R336.2 U28.11 | length 419.3
  Top Layer w10: U28.11@5637.69,5031.12 v1(5637.69,5110) 5637.69,5176.19 C238.2@5640,5178.5
  Top Layer w15: v1(5767,4947) R336.2@5821.38,4947
  Bottom Layer w15: v1(5637.69,5110) 5767,4980.69 v1(5767,4947)
NetC239_2: C239.2 R337.2 U29.11 | length 395.5
  Top Layer w10: U29.11@5639.69,5895.12 v1(5639.69,5970) C239.2@5639.69,6028.5
  Top Layer w15: v1(5778,5828) 5779,5827 R337.2@5840.38,5827
  Bottom Layer w15: v1(5639.69,5970) 5639.69,5966.31 v1(5778,5828)
NetC240_2: C240.2 R253.2 R254.1 | length 175.2
  Top Layer w20: R254.1@5790.98,5190.47 5809.53,5190.47 5832.52,5167.48 R253.2@5869.69,5167.48 C240.2@5869.69,5080.47
NetC241_2: C241.2 R255.2 R256.1 | length 169.5
  Top Layer w20: R256.1@5789.69,6051.5 5795.67,6057.48 R255.2@5869.69,6057.48 C241.2@5869.69,5970.47
NetC242_1: C242.1 R265.2 U30.16 | length 486.5
  Top Layer w10: U30.16@4780,5192.44 4780,5130 4812.13,5097.87 4989.1,5097.87 5048.48,5038.48 C242.1@5048.48,5000
  Top Layer w20: R265.2@5041.79,4923.62 5041.79,4993.31 C242.1@5048.48,5000
NetC242_2: C242.2 R266.2 U30.17 | length 521.1
  Top Layer w10: U30.17@4799.69,5192.44 4799.69,5140.31 4824.25,5115.75 5034.25,5115.75 5111.48,5038.52 C242.2@5111.48,5000
  Top Layer w20: C242.2@5111.48,5000 5111.79,4999.69 R266.2@5111.79,4923.62
NetC243_1: C243.1 R267.2 U30.18 | length 572.2
  Top Layer w10: U30.18@4819.37,5192.44 4819.37,5160.63 4846.38,5133.62 5096.38,5133.62 5190,5040 5190,5001.52 C243.1@5188.48,5000
  Top Layer w20: R267.2@5181.79,4923.62 5181.79,4993.31 C243.1@5188.48,5000
NetC243_2: C243.2 R269.2 U30.19 | length 602.2
  Top Layer w10: U30.19@4839.06,5192.44 4839.06,5166.22 4853.78,5151.5 5148.5,5151.5 5251.48,5048.52 C243.2@5251.48,5000
  Top Layer w20: 5250,4980 5259.9,4970.1 R269.2@5259.9,4917.8
NetC244_2: C244.2 R271.2 U28.12 | length 197.5
  Top Layer w10: C244.2@5560.98,5137.48 5560.98,5129.02 5612.09,5077.91 U28.12@5612.09,5031.12
  Top Layer w20: R271.2@5490.98,5137.48 C244.2@5560.98,5137.48
NetC245_2: C245.2 R273.2 U29.12 | length 185.9
  Top Layer w10: C245.2@5559.69,5988.5 5559.69,5981.34 5614.09,5926.93 U29.12@5614.09,5895.12
  Top Layer w20: R273.2@5489.69,5988.5 C245.2@5559.69,5988.5
NetC246_1: C246.1 R274.2 U30.21 | length 621.4
  Top Layer w10: U30.21@4819.37,5424.72 4819.37,5479.37 4844.25,5504.25 5134.25,5504.25 5232.26,5602.26 C246.1@5232.26,5628.26
  Top Layer w20: C246.1@5232.26,5628.26 5233.76,5629.76 R274.2@5233.76,5704.64
NetC246_2: C246.2 R276.2 U30.20 | length 668.4
  Top Layer w10: U30.20@4839.06,5424.72 4839.06,5469.06 4856.38,5486.38 5183.08,5486.38 5297.76,5601.06 5295.26,5603.57 C246.2@5295.26,5628.26
  Top Layer w20: C246.2@5295.26,5628.26 5299.92,5632.93 R276.2@5299.92,5708.82
NetC247_1: C247.1 R277.2 U30.23 | length 522.1
  Top Layer w10: U30.23@4780,5424.72 4780,5490 4783.62,5493.62 4783.62,5494.18 4829.44,5540 5030,5540 5086.31,5596.31 C247.1@5086.31,5625.46
  Top Layer w20: C247.1@5086.31,5625.46 5087.81,5626.96 R277.2@5087.81,5701.84
NetC247_2: C247.2 R278.2 U30.22 | length 563.3
  Top Layer w10: U30.22@4799.69,5424.72 4799.69,5479.69 4801.5,5481.5 4801.5,5486.77 4836.85,5522.13 5072.13,5522.13 5149.31,5599.31 C247.2@5149.31,5625.46
  Top Layer w20: C247.2@5149.31,5625.46 5157.81,5633.97 R278.2@5157.81,5701.84
NetC248_2: C248.2 R270.2 R271.1 | length 179.9
  Top Layer w20: C248.2@5409.69,5090.47 R270.2@5409.69,5177.48 5438.29,5177.48 5463.78,5202.98 5488.48,5202.98 R271.1@5490.98,5200.47
NetC249_1: C249.1 R279.2 U30.25 | length 427.7
  Top Layer w10: U30.25@4740.63,5424.72 4740.63,5510.63 4807.36,5577.36 4917.36,5577.36 4940.31,5600.31 C249.1@4940.31,5629.76
  Top Layer w20: C249.1@4940.31,5629.76 4941.81,5631.26 R279.2@4941.81,5704.64
NetC249_2: C249.2 R280.2 U30.24 | length 463.7
  Top Layer w10: U30.24@4760.31,5424.72 4760.31,5490.31 4762.13,5492.13 4762.13,5497.4 4765.75,5501.03 4765.75,5501.58 4822.04,5557.87 4827.87,5557.87 4829.49,5559.49 4959.49,5559.49 5003.31,5603.31 C249.2@5003.31,5629.76
  Top Layer w20: C249.2@5003.31,5629.76 5011.81,5638.26 R280.2@5011.81,5704.64
NetC250_2: C250.2 R272.2 R273.1 | length 166.5
  Top Layer w20: C250.2@5409.69,5970.47 R272.2@5409.69,6047.48 5427.48,6047.48 5450.47,6070.47 R273.1@5489.69,6070.47
NetC251_1: C251.1 U30.5 | length 299.8
  Top Layer w10: C251.1@4461,4963 C251.1@4461,4943 4470,4952 4470,5030 4562.56,5122.56 4562.56,5178.19 U30.5@4564.37,5180
NetC252_1: C252.1 C253.1 U30.7 | length 367.5
  Top Layer w10: U30.7@4602.83,5192.44 4601.93,5191.54 4601.93,5163.01 4600.12,5161.2 4600.12,5155.6 4600,5155.49 4600,5140 4604.65,5135.35 4604.65,5084.45 4633.31,5055.79 4633.31,4973 C253.1@4642.5,4973
  Top Layer w30: C253.1@4642.5,4973 4675.96,4939.54 C252.1@4675.96,4863
NetC254_1: C254.1 R281.2 U30.27 | length 330.8
  Top Layer w10: U30.27@4701.26,5424.72 4701.26,5561.26 4780,5640 C254.1@4791.78,5640
  Top Layer w20: R281.2@4791.81,5704.64 4791.81,5639.97 C254.1@4796.31,5635.46
NetC254_2: C254.2 R282.2 U30.26 | length 367.6
  Top Layer w10: U30.26@4720.94,5424.72 4720.94,5520.94 4800,5600 4850,5600 4859.31,5609.31 C254.2@4859.31,5635.46
  Top Layer w20: C254.2@4859.31,5635.46 4861.81,5637.97 R282.2@4861.81,5704.64
NetC255_1: C255.1 R283.2 U30.12 | length 298.1
  Top Layer w10: U30.12@4701.26,5192.44 4701.26,5057.74 C255.1@4760.3,4998.7
  Top Layer w20: R283.2@4751.79,4922.32 4751.79,4990.2 C255.1@4760.3,4998.7
NetC255_2: C255.2 R284.2 U30.13 | length 345.3
  Top Layer w10: U30.13@4720.94,5192.44 4720.94,5079.06 4760,5040 4810,5040 4823.29,5026.71 C255.2@4823.29,4998.7
  Top Layer w20: C255.2@4823.29,4998.7 4823.29,4930.83 R284.2@4831.79,4922.32
NetC256_1: C256.1 R285.2 U30.14 | length 406.3
  Top Layer w10: U30.14@4740.63,5192.44 4740.63,5089.37 4770,5060 4880,5060 4908.5,5031.5 C256.1@4908.5,5000
  Top Layer w20: R285.2@4900,4923.62 4900,4991.5 C256.1@4908.5,5000
NetC256_2: C256.2 R286.2 U30.15 | length 430.9
  Top Layer w10: U30.15@4760.31,5192.44 4760.31,5109.69 4790,5080 4916.26,5080 4971.5,5024.76 C256.2@4971.5,5000
  Top Layer w20: R286.2@4970,4923.62 4970,4998.5 C256.2@4971.5,5000
NetC257_2: C257.2 R288.2 U29.3 | length 204.9
  Top Layer w10: C257.2@5559.69,5550.47 5559.69,5568.64 5614.09,5623.05 U29.3@5614.09,5662.83
  Top Layer w20: R288.2@5489.69,5550.47 C257.2@5559.69,5550.47
NetC258_2: C258.2 R290.2 U28.3 | length 200.1
  Top Layer w10: C258.2@5559.69,4690.47 5559.69,4709.69 5612.09,4762.09 U28.3@5612.09,4798.83
  Top Layer w20: R290.2@5489.69,4690.47 C258.2@5559.69,4690.47
NetC259_2: C259.2 R287.2 R288.1 | length 192.7
  Top Layer w20: C259.2@5409.69,5617.48 R287.2@5409.69,5520.47 5412.19,5522.98 5436.89,5522.98 5472.38,5487.48 R288.1@5489.69,5487.48
NetC260_2: C260.2 R289.2 R290.1 | length 177
  Top Layer w20: C260.2@5420,4738.5 5410,4728.5 R289.2@5410,4661.5 5412.5,4664 5437.2,4664 5473.72,4627.48 R290.1@5489.69,4627.48
NetC262_2: C262.2 R293.2 U28.5 | length 197.3
  Top Layer w10: U28.5@5663.28,4798.83 5663.28,4756.72 5719.69,4700.31 C262.2@5719.69,4694.92
  Top Layer w20: C262.2@5719.69,4694.92 R293.2@5789.69,4694.92
NetC263_2: C263.2 R297.2 U29.5 | length 194.9
  Top Layer w10: U29.5@5665.28,5662.83 5665.28,5614.88 C263.2@5719.69,5560.47
  Top Layer w20: C263.2@5719.69,5560.47 R297.2@5789.69,5560.47
NetC264_2: C264.2 R292.2 R293.1 | length 165.8
  Top Layer w20: R293.1@5789.69,4631.93 5790.66,4631.93 5832.73,4674 5857.5,4674 R292.2@5860,4671.5 C264.2@5860,4748.5
NetC265_2: C265.2 R296.2 R297.1 | length 184.8
  Top Layer w20: R297.1@5789.69,5497.48 5807.48,5497.48 5850.47,5540.47 R296.2@5869.69,5540.47 C265.2@5869.69,5627.48
NetD7_1: D7.1 Q1.1 Q1.2 Q1.5 Q1.6 Q1.8 | length 316.1
  Top Layer w10: Q1.2@3111.62,5030 3130,5030 Q1.5@3188.39,5030 ; Q1.1@3111.62,5055.59 3137.21,5055.59 Q1.8@3150,5042.8 3157.2,5050 3170,5050 3175.59,5055.59 Q1.6@3188.39,5055.59
  Top Layer w30: D7.1@3099.37,5150 3140,5150 3150,5140 Q1.8@3150,5042.8
NetD7_2: D7.2 R39.1 | length 79.1
  Top Layer w30: R39.1@2941.5,5150 D7.2@3020.63,5150
NetD10_1: D10.1 R46.1 U7.23 | length 466.9
  Top Layer w10: D10.1@3026.93,6290.57 3026.93,6346.93 3070,6390 3070,6450 3085.04,6465.04 U7.23@3122.13,6465.04
  Top Layer w30: R46.1@2796.93,6287.48 3023.84,6287.48 D10.1@3026.93,6290.57
NetD10_2: D10.2 L1.2 U7.1 U7.24 | length 545.2
  Top Layer w10: 3140,6400 3147.72,6407.72 U7.1@3147.72,6419.77
  Top Layer w20: 3115,6412.88 3142,6412.88
  Top Layer w30: L1.2@2856.93,6181.65 3010.02,6181.65 D10.2@3026.93,6198.57 3081.57,6198.57 3123,6240 ; 3113,6400 3113,6433.44 3116.72,6437.17 3117,6437.17
  Top Layer w40: 3123,6240 3123,6406
NetD13_1: D13.1 R48.1 | length 69
  Top Layer w30: R48.1@4061.32,6174.25 D13.1@4061.32,6243.23
NetD15_1: D15.1 L2.1 U7.13 U7.14 | length 644.4
  Top Layer w10: U7.14@3226.46,6569.37 3226.46,6586.46 3230,6590 3240,6590 ; 3235.02,6572.74 3246.14,6583.86 U7.13@3246.14,6569.37 ; 3419.1,6572.74 D15.1@3486.93,6640.57
  Top Layer w30: 3235.02,6572.74 3419.1,6572.74 ; D15.1@3486.93,6640.57 3490,6643.64 3490,6730 3541.65,6781.65 L2.1@3680,6781.65
NetD17_1: D17.1 R64.1 | length 118.7
  Top Layer w30: R64.1@3386.18,5568.9 3386.65,5568.42 D17.1@3386.65,5450.39
NetD24_1: D24.1 Q3.1 Q3.2 Q3.5 Q3.6 Q3.8 | length 281.3
  Top Layer w10: Q3.6@3971.61,1824.41 3997.2,1824.41 Q3.8@4010,1837.2 4022.8,1824.41 Q3.1@4048.39,1824.41 ; Q3.5@3971.61,1850 Q3.2@4048.39,1850
  Top Layer w30: Q3.8@4010,1837.2 4009.99,1753.98 D24.1@4033.98,1730
NetD24_2: D24.2 R111.1 | length 73.3
  Top Layer w30: D24.2@4112.72,1730 4171.85,1730 R111.1@4181.85,1740
NetD33_1: D33.1 Q4.1 Q4.2 Q4.5 Q4.6 Q4.8 | length 322
  Top Layer w10: Q4.2@3123.98,3200 3140,3200 3152.8,3212.8 Q4.8@3162.36,3212.8 ; Q4.1@3123.98,3225.59 3149.57,3225.59 Q4.8@3160,3215.16 ; Q4.5@3200.75,3200 3175.16,3200 Q4.8@3162.36,3212.8 ; Q4.6@3200.75,3225.59 3175.16,3225.59 Q4.8@3162.36,3212.8
  Top Layer w30: D33.1@3111.73,3320 3150,3320 3160,3310 3160,3215.16 Q4.8@3162.36,3212.8
NetD33_2: D33.2 R156.1 | length 79.1
  Top Layer w30: R156.1@2953.86,3320 D33.2@3032.99,3320
NetD42_1: D42.1 Q5.1 Q5.2 Q5.5 Q5.6 Q5.8 | length 284.6
  Top Layer w10: Q5.6@4013.66,3684.41 4039.25,3684.41 Q5.8@4052.04,3697.2 ; Q5.5@4013.66,3710 4039.25,3710 Q5.8@4052.04,3697.2 ; Q5.1@4090.43,3684.41 4064.84,3684.41 Q5.8@4052.04,3697.2 ; Q5.2@4090.43,3710 4064.84,3710 Q5.8@4052.04,3697.2
  Top Layer w30: Q5.8@4052.04,3697.2 4052.04,3630.63 D42.1@4082.68,3600
NetD42_2: D42.2 R201.1 | length 73.3
  Top Layer w30: D42.2@4161.42,3600 4220.55,3600 R201.1@4230.55,3610
NetD51_1: D51.1 Q6.1 Q6.2 Q6.5 Q6.6 Q6.8 | length 283.3
  Top Layer w10: Q6.2@3311.61,1250 3337.2,1250 Q6.8@3350,1262.8 ; Q6.1@3311.61,1275.59 3337.2,1275.59 Q6.8@3350,1262.8 ; 3370,1250 Q6.5@3388.39,1250 ; Q6.6@3388.39,1275.59 3362.8,1275.59 Q6.8@3350,1262.8
  Top Layer w30: D51.1@3295.73,1374.17 3350.01,1319.89 Q6.8@3350,1262.8
NetD51_2: D51.2 R246.1 | length 59.1
  Top Layer w30: R246.1@3157.86,1374.17 D51.2@3216.99,1374.17
NetD60_1: D60.1 Q7.1 Q7.2 Q7.5 Q7.6 Q7.8 | length 262.5
  Top Layer w10: Q7.6@4031.61,5626.84 4063.15,5626.84 4069.99,5620 ; Q7.5@4031.61,5652.43 4057.2,5652.43 Q7.8@4069.99,5639.64 ; Q7.1@4108.38,5626.84 4082.79,5626.84 Q7.8@4069.99,5639.64 ; Q7.2@4108.38,5652.43 4082.79,5652.43 Q7.8@4069.99,5639.64
  Top Layer w30: 4069.99,5620 4069.99,5573.08 D60.1@4100.63,5542.44
NetD60_2: D60.2 R291.1 | length 89.1
  Top Layer w30: D60.2@4179.37,5542.44 R291.1@4268.5,5542.44
NetQ1_3: Q1.3 R43.1 | length 101.5
  Top Layer w10: R43.1@3050,5051.5 3074.76,5051.5 3077.27,5054 3089.89,5041.38 3089.89,5010.11 3095.59,5004.41 Q1.3@3111.62,5004.41
NetQ2_3: Q2.3 R72.1 | length 85.2
  Top Layer w20: R72.1@2121.5,6121.97 2171.61,6172.09 Q2.3@2171.61,6186.38
NetQ3_3: Q3.3 R115.1 | length 74.5
  Top Layer w10: Q3.3@4048.39,1875.59 4056.26,1875.59 R115.1@4103.35,1828.5
NetQ4_3: Q4.3 R160.1 | length 102.9
  Top Layer w10: R160.1@3062.36,3221.5 3087.12,3221.5 3089.63,3224 3100,3213.63 3100,3180 3105.59,3174.41 Q4.3@3123.98,3174.41
NetQ5_3: Q5.3 R205.1 | length 90.3
  Top Layer w10: Q5.3@4090.43,3735.59 4104.41,3735.59 4112.16,3727.84 4112.16,3708.62 4124.78,3696 4127.29,3698.5 R205.1@4152.05,3698.5
NetQ6_3: Q6.3 R250.1 | length 110.4
  Top Layer w10: R250.1@3248.25,1281.5 3278.39,1281.5 3289.88,1270 3289.88,1230.12 3295.59,1224.41 Q6.3@3311.61,1224.41
NetQ7_3: Q7.3 R295.1 | length 90.7
  Top Layer w10: Q7.3@4108.38,5678.02 4121.98,5678.02 4130.11,5669.89 4130.11,5650 4131.18,5650 4142.73,5638.44 4167.5,5638.44 R295.1@4170,5640.95
NetR16_1: R16.1 U3.2 | length 243.1
  Top Layer w10: U3.2@2695.74,5406.14 2695.74,5445.74 2770,5520 R16.1@2868.5,5519.95 R16.1@2868.5,5519.95
NetR23_1: R23.1 U3.3 | length 254.6
  Top Layer w10: U3.3@2676.05,5406.14 2676.05,5363.95 2700.05,5339.95 R23.1@2878.5,5339.95
NetR42_2: R42.2 U4.2 | length 93.4
  Top Layer w10: R42.2@2790,5038.5 2808.5,5020 U4.2@2875.71,5020
NetR43_2: R43.2 U4.4 | length 88.2
  Top Layer w10: U4.4@2964.29,4994.41 3044.09,4994.41 R43.2@3050,4988.5
NetR51_1: R51.1 U7.18 | length 138.1
  Top Layer w10: R51.1@3081.5,6680 3081.5,6668.5 3147.72,6602.28 U7.18@3147.72,6569.37
NetR52_2: R52.2 R53.1 R55.2 | length 225.3
  Top Layer w30: R52.2@3190,6834.76 R55.2@3270,6834.76 3315.24,6834.76 3366.93,6783.07 R53.1@3366.93,6756.06
NetR57_1: R57.1 U7.21 | length 211
  Top Layer w10: R57.1@2948.43,6594.57 3022.99,6520 3060,6520 3075.59,6504.41 U7.21@3122.13,6504.41
NetR65_2: R65.2 U8.2 | length 165.5
  Top Layer w12: R65.2@4881.5,6500 4940,6500 4980.31,6459.69 U8.2@5030.28,6459.69
NetR66_1: R66.1 U8.8 | length 407
  Top Layer w10: U8.8@5140.51,6440 5501.2,6440 5514,6427.2 5511.5,6424.7 R66.1@5511.5,6400
NetR71_2: R71.2 U11.2 | length 144.8
  Top Layer w10: U11.2@2220,6106.26 2220,6140.31 2240,6160.31 2279.84,6160.31 R71.2@2310,6190.47
NetR72_2: R72.2 U11.4 | length 214.3
  Top Layer w20: R72.2@2058.5,6121.97 2058.5,6061.81 2102.64,6017.68 U11.4@2194.41,6017.68
NetR88_1: R88.1 U14.2 | length 198.6
  Top Layer w10: R88.1@4283.54,1470 4410,1470 4424.57,1455.43 U14.2@4424.57,1403.86
NetR95_1: R95.1 U14.3 | length 209.4
  Top Layer w10: R95.1@4283.54,1350 4293.54,1340 4410.13,1340 4410.13,1342.37 4431.18,1363.43 4432.35,1363.43 4443.35,1374.43 4443.35,1375.59 4444.25,1376.5 U14.3@4444.25,1403.86
NetR114_2: R114.2 U15.2 | length 96.2
  Top Layer w10: U15.2@4267.64,1860 4323.54,1860 R114.2@4352.05,1831.5
NetR115_2: R115.2 U15.4 | length 78.2
  Top Layer w10: R115.2@4103.35,1891.5 4109.25,1885.59 U15.4@4179.06,1885.59
NetR133_1: R133.1 U18.2 | length 247.6
  Top Layer w10: U18.2@2708.1,3586.09 2708.1,3638.1 2710.13,3640.13 2712.37,3640.13 2729.87,3657.63 2729.87,3659.87 2759.95,3689.95 R133.1@2880.87,3689.95
NetR140_1: R140.1 U18.3 | length 271.8
  Top Layer w10: U18.3@2688.41,3586.09 2688.41,3521.59 2700.05,3509.95 R140.1@2890.87,3509.95
NetR159_2: R159.2 U19.2 | length 93.4
  Top Layer w10: R159.2@2802.36,3208.5 2820.87,3190 U19.2@2888.07,3190
NetR160_2: R160.2 U19.4 | length 88.2
  Top Layer w10: U19.4@2976.65,3164.41 3056.46,3164.41 R160.2@3062.36,3158.5
NetR178_1: R178.1 U22.2 | length 206.1
  Top Layer w10: R178.1@4353.54,3340 4459.13,3340 4494.57,3304.57 U22.2@4494.57,3254.17
NetR185_1: R185.1 U22.3 | length 200.7
  Top Layer w10: R185.1@4353.54,3220 4363.54,3210 4500,3210 4514.25,3224.25 U22.3@4514.25,3254.17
